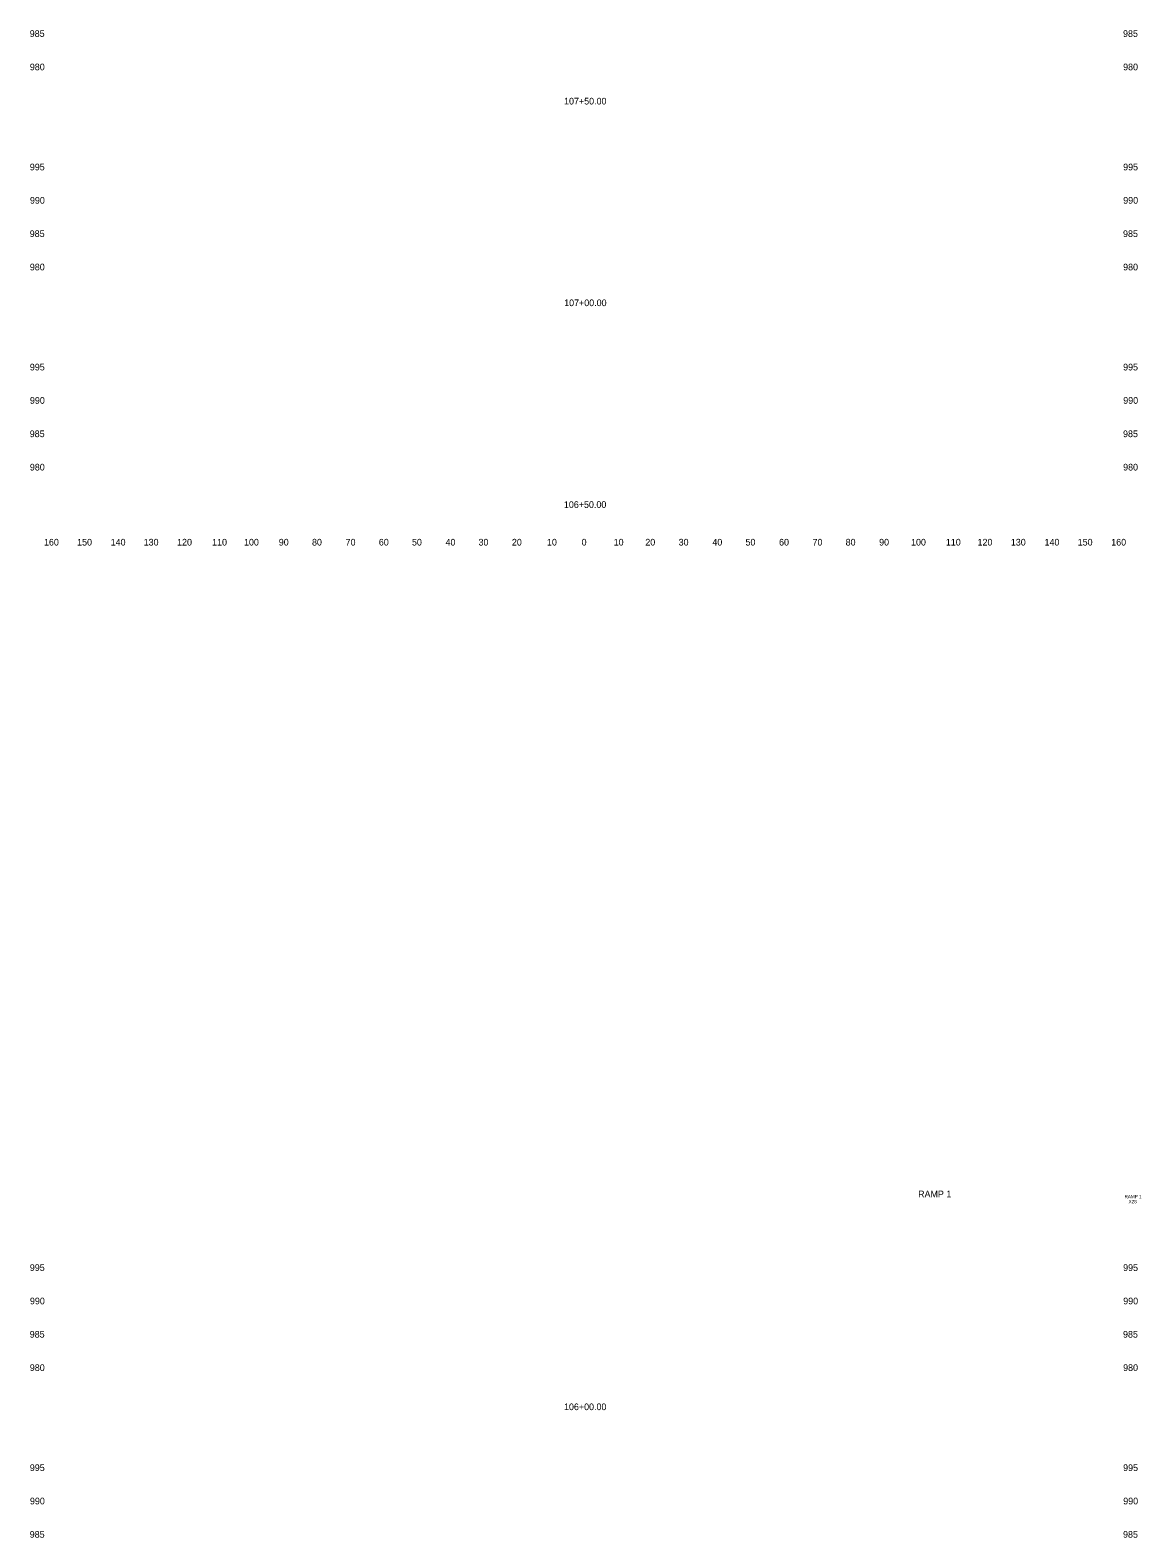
# Model space of a CAD drawing. Extents: x 4994 to 7869, y 4997 to 8804.
# Drawn here: x 6024 to 6357, y 7900 to 8352 of the extents above; entities that cross this region are included whole.
import ezdxf

# ---------------------------------------------------------------- set-up
doc = ezdxf.new("R2010")
doc.units = 0
for name, color, linetype in [('RD_SHT_ID', 7, 'Continuous'), ('RD_XS_TX_Offset', 7, 'Continuous'), ('RD_XS_TX_Station', 7, 'Continuous')]:
    doc.layers.add(name, color=color, linetype=linetype)

msp = doc.modelspace()

# ---------------------------------------------------------------- texts
at = {"layer": 'RD_SHT_ID'}
for s, height, p in [('RAMP 1', 2, (6290.19, 8002.06)), ('RAMP 1', 1, (6352.06, 8001.8)), ('X28', 1, (6353.29, 8000.3))]:
    msp.add_text(s, height=height, dxfattribs=at).set_placement(p)
at = {"layer": 'RD_XS_TX_Offset'}
for s, p in [('985', (6023.83, 8350)), ('985', (6351.63, 8350)), ('980', (6023.86, 8340)), ('980', (6351.66, 8340)), ('995', (6023.86, 8310)), ('995', (6351.66, 8310)), ('990', (6023.89, 8300)), ('990', (6351.69, 8300)), ('985', (6023.83, 8290)), ('985', (6351.63, 8290)), ('980', (6023.86, 8280)), ('980', (6351.66, 8280)), ('995', (6023.86, 8250)), ('995', (6351.66, 8250)), ('990', (6023.89, 8240)), ('990', (6351.69, 8240)), ('985', (6023.83, 8230)), ('985', (6351.63, 8230)), ('980', (6023.86, 8220)), ('980', (6351.66, 8220)), ('160', (6028.1, 8197.5)), ('150', (6038.04, 8197.5)), ('140', (6048.1, 8197.5)), ('130', (6057.99, 8197.5)), ('120', (6068.01, 8197.5)), ('110', (6078.51, 8197.5)), ('100', (6088.07, 8197.5)), ('90', (6098.5, 8197.5)), ('80', (6108.46, 8197.5)), ('70', (6118.54, 8197.5)), ('60', (6128.5, 8197.5)), ('50', (6138.43, 8197.5)), ('40', (6148.5, 8197.5)), ('30', (6158.39, 8197.5)), ('20', (6168.4, 8197.5)), ('10', (6178.91, 8197.5)), ('0', (6189.3, 8197.5)), ('0', (6189.3, 8197.5)), ('10', (6198.91, 8197.5)), ('20', (6208.4, 8197.5)), ('30', (6218.39, 8197.5)), ('40', (6228.5, 8197.5)), ('50', (6238.43, 8197.5)), ('60', (6248.5, 8197.5)), ('70', (6258.54, 8197.5)), ('80', (6268.46, 8197.5)), ('90', (6278.5, 8197.5)), ('100', (6288.07, 8197.5)), ('110', (6298.51, 8197.5)), ('120', (6308.01, 8197.5)), ('130', (6317.99, 8197.5)), ('140', (6328.1, 8197.5)), ('150', (6338.04, 8197.5)), ('160', (6348.1, 8197.5)), ('995', (6023.86, 7980)), ('995', (6351.66, 7980)), ('990', (6023.89, 7970)), ('990', (6351.69, 7970)), ('985', (6023.83, 7960)), ('985', (6351.63, 7960)), ('980', (6023.86, 7950)), ('980', (6351.66, 7950)), ('995', (6023.86, 7920)), ('995', (6351.66, 7920)), ('990', (6023.89, 7910)), ('990', (6351.69, 7910)), ('985', (6023.83, 7900)), ('985', (6351.63, 7900))]:
    msp.add_text(s, height=2, dxfattribs=at).set_placement(p)
at = {"layer": 'RD_XS_TX_Station'}
for s, p in [('107+50.00', (6184.04, 8329.74)), ('107+00.00', (6184.07, 8269.28)), ('106+50.00', (6183.99, 8208.78)), ('106+00.00', (6184.02, 7938.26))]:
    msp.add_text(s, height=2, dxfattribs=at).set_placement(p)

doc.saveas('drawing.dxf')
